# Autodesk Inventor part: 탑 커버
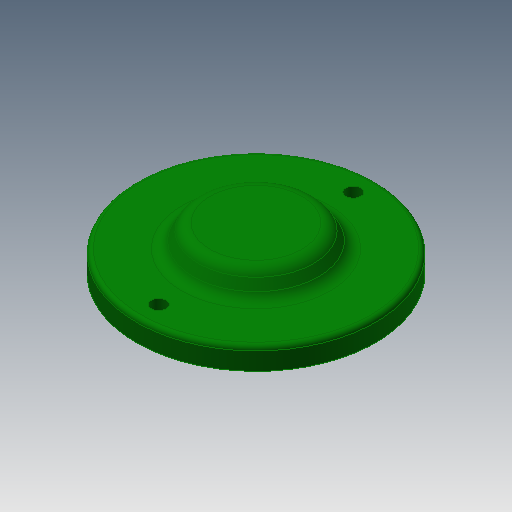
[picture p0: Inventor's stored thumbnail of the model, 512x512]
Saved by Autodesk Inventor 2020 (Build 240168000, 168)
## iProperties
Created: 2017-05
Part Number: 탑 커버
Material: 알루미늄 6061
Document SubType Name: Modeling
Designer: mduedu
Density: 1 g/cm^3
Appearance: 진녹색
Author: mduedu
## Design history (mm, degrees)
sketch "스케치1"
  geometry: C1 r 27 at (0, 0); 1 further point
  constraints: 1 centre point, 1 coincident
  dimensions: "d31" = 54 diameter of C1
extrude "돌출1" new body sketch "스케치1" distance "d2" = 5; taper "d3" = 0 deg
sketch "스케치2"
  geometry: C1 r 15 at (0, 0); 1 further point
  constraints: 1 centre point, 1 coincident
  dimensions: "d5" = 30 diameter of C1
extrude "돌출2" join sketch "스케치2" distance "d6" = 5; taper "d7" = -30 deg
sketch "스케치3"
  geometry: C1 r 16 at (0, 0); 1 further point
  constraints: 1 centre point, 1 coincident
  dimensions: "d32" = 32 diameter of C1
extrude "돌출3" join sketch "스케치3" distance "d10" = 3; taper "d11" = 0 deg
sketch "스케치4"
  geometry: C1 r 16 at (0, 0) reference; C2 r 13 at (0, 0); 1 further point
  constraints: 1 centre point
  dimensions: "d33" = 3 radial gap between concentric circles of C2 C1
extrude "돌출4" cut sketch "스케치4" distance "d14" = 6; taper "d15" = 0 deg
chamfer "모따기1" distance "d16" = 1; stored, may be unused: second distance "d17" = 2, angle "d18" = 45 deg
fillet "모깎기3" dims "d19" = 3
fillet "모깎기4" dims "d20" = 1
fillet "모깎기5" dims "d21" = 1
sketch "스케치5" dims "d34" = 44
  geometry: C1 r 27 at (0, 0) reference; 2 further points
  constraints: 2 vertical alignment, 1 coincident, 2 other
hole "구멍2" sketch "스케치5" at (0, 22) diameter "d35" = 3.4; stored, may be unused: countersink angle "d39" = 90 deg, drill point angle "d41" = 118 deg; dims "d36" = 6, "d37" = 4, "d38" = 2, "d40" = 8
node "솔리드1"
pattern_circular "원형 패턴1" dims angle "d43" = 360 deg
node "투영된 루프2"
